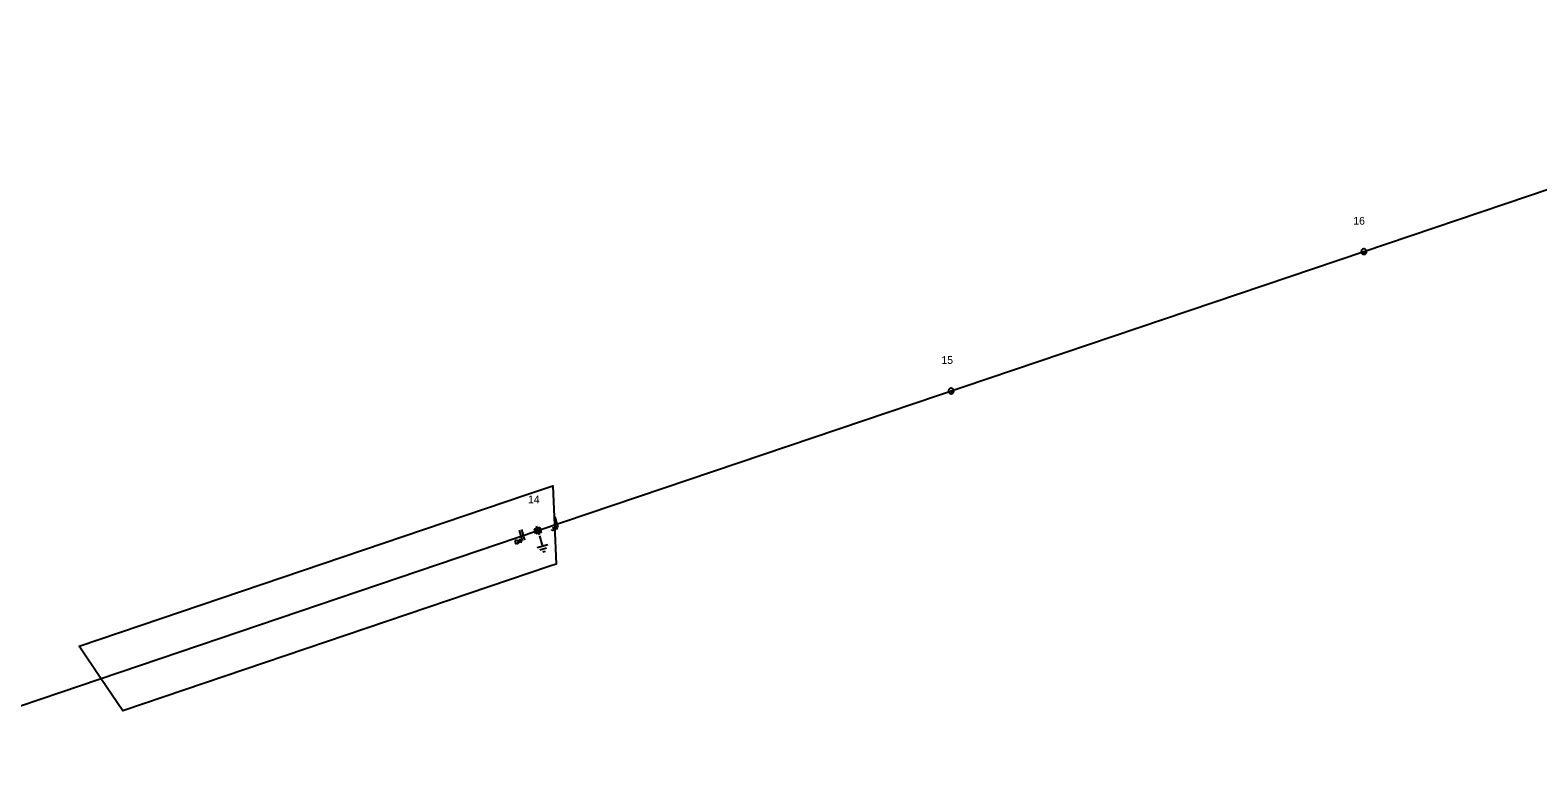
# Model space of a CAD drawing. Extents: x -788491 to -785797, y -1154753 to -1152002.
# Drawn here: x -786477.8 to -786137.2, y -1153308.2 to -1153143.3 of the extents above; entities that cross this region are included whole.
import ezdxf

# ---------------------------------------------------------------- set-up
doc = ezdxf.new("R2010")
doc.units = 0
for name, color, linetype in [('Vrstva 1', 7, 'Continuous'), ('Vrstva 13', 7, 'Continuous'), ('Vrstva 14', 7, 'Continuous'), ('Vrstva 15', 7, 'Continuous'), ('Vrstva 18', 7, 'Continuous'), ('Vrstva 2', 7, 'Continuous'), ('Vrstva 35', 7, 'Continuous')]:
    doc.layers.add(name, color=color, linetype=linetype)

# ---------------------------------------------------------------- blocks, each defined once
blk = doc.blocks.new('VN850')
at = {"layer": 'Vrstva 15'}
for points in [[(-0.56, 1.43), (-0.56, -1.07)], [(-0.01, 1.43), (-0.01, -1.07)], [(-2.09, -0.54), (-1.78, -0.54)], [(-2.09, -1.41), (-2.09, -0.54)], [(-1.78, -1.41), (-2.09, -1.41)], [(-1.78, -0.54), (-1.66, -0.6)], [(-1.67, -1.35), (-1.78, -1.41)], [(-1.59, -1.2), (-1.67, -1.35)], [(-1.66, -0.6), (-1.59, -0.75)], [(-1.59, -0.75), (-1.55, -0.96)], [(-1.55, -0.96), (-1.59, -1.2)], [(-1.26, -0.54), (-1.26, -1.41)], [(-0.85, -0.54), (-1.26, -1.09)], [(-1.13, -0.92), (-0.77, -1.41)]]:
    blk.add_lwpolyline(points, dxfattribs=at)
blk = doc.blocks.new('VN840')
at = {"layer": 'Vrstva 15'}
for points in [[(-0.01, 1.41), (-0.01, -1.09)], [(-1.51, -1.24), (-1.51, -1.15)], [(-1.48, -1.35), (-1.51, -1.24)], [(-1.33, -1.42), (-1.48, -1.35)], [(-1.27, -1.42), (-1.33, -1.42)], [(-1.13, -1.35), (-1.27, -1.42)], [(-1.09, -1.24), (-1.13, -1.35)], [(-1.09, -0.59), (-1.09, -1.24)], [(-0.68, -0.59), (-0.68, -1.42)], [(-0.68, -1.11), (-0.27, -0.59)], [(-0.54, -0.94), (-0.2, -1.42)]]:
    blk.add_lwpolyline(points, dxfattribs=at)
blk = doc.blocks.new('VN440')
at = {"layer": 'Vrstva 2'}
for points in [[(1.22, 0), (1.21, 0.13), (1.19, 0.25), (1.16, 0.38), (1.11, 0.5), (1.05, 0.61), (0.98, 0.72), (0.9, 0.82), (0.81, 0.91), (0.71, 0.99), (0.6, 1.06), (0.49, 1.12), (0.37, 1.16), (0.25, 1.2), (0.12, 1.22), (-0.01, 1.22), (-0.14, 1.22), (-0.26, 1.2), (-0.39, 1.16), (-0.51, 1.12), (-0.62, 1.06), (-0.73, 0.99), (-0.83, 0.91), (-0.92, 0.82), (-1, 0.72), (-1.07, 0.61), (-1.13, 0.5), (-1.18, 0.38), (-1.21, 0.25), (-1.23, 0.13), (-1.24, 0), (-1.23, -0.13), (-1.21, -0.26), (-1.18, -0.38), (-1.13, -0.5), (-1.07, -0.62), (-1, -0.73), (-0.92, -0.83), (-0.83, -0.92), (-0.73, -1), (-0.62, -1.07), (-0.51, -1.13), (-0.39, -1.17), (-0.26, -1.2), (-0.14, -1.23), (-0.01, -1.23), (0.12, -1.23), (0.25, -1.2), (0.37, -1.17), (0.49, -1.13), (0.6, -1.07), (0.71, -1), (0.81, -0.92), (0.9, -0.83), (0.98, -0.73), (1.05, -0.62), (1.11, -0.5), (1.16, -0.38), (1.19, -0.26), (1.21, -0.13), (1.22, 0)], [(-1.24, 0), (1.22, 0)], [(-1.18, -0.34), (1.1, -0.34)], [(-1.01, -0.63), (0.97, -0.63)], [(-0.74, -0.92), (0.68, -0.92)]]:
    blk.add_lwpolyline(points, dxfattribs=at)
blk = doc.blocks.new('VN810')
at = {"layer": 'Vrstva 14'}
for points in [[(0, -1.25), (0, -3.75)], [(1.25, -3.75), (-1.25, -3.75)], [(0.77, -4.37), (-0.8, -4.37)], [(0, -5), (-0.25, -5)], [(0.27, -5), (0, -5)]]:
    blk.add_lwpolyline(points, dxfattribs=at)
blk = doc.blocks.new('VN470')
at = {"layer": 'Vrstva 2'}
for points in [[(-1.23, 1.22), (1.23, 1.22)], [(-1.23, -1.23), (-1.23, 1.22)], [(-0.92, 0.9), (0.92, 0.9)], [(-0.92, -0.95), (-0.92, 0.9)], [(-0.61, 0.61), (0.61, 0.61)], [(-0.61, -0.62), (-0.61, 0.61)], [(-0.31, -0.27), (-0.31, 0.34)], [(-0.31, 0.34), (0.31, 0.34)], [(0, 1.22), (0, 1.97)], [(0.31, 0.34), (0.31, -0.27)], [(0.61, 0.61), (0.61, -0.62)], [(0.92, 0.9), (0.92, -0.95)], [(1.23, 1.22), (1.23, -1.23)], [(1.23, -1.23), (-1.23, -1.23)], [(0.92, -0.95), (-0.92, -0.95)], [(0.61, -0.62), (-0.61, -0.62)], [(0.31, -0.27), (-0.31, -0.27)], [(0, -1.23), (0, -1.98)]]:
    blk.add_lwpolyline(points, dxfattribs=at)

msp = doc.modelspace()

# ---------------------------------------------------------------- linework, layer by layer
at = {"layer": 'Vrstva 1'}
msp.add_lwpolyline([(-786516.04, -1153308.16), (-786363.07, -1153256.35), (-786176.45, -1153193.34), (-786028.55, -1153143.31)], dxfattribs=at)
at = {"layer": 'Vrstva 35'}
msp.add_lwpolyline([(-786359.32, -1153255.09), (-786358.94, -1153263.93), (-786360.34, -1153264.4), (-786456.85, -1153297.09), (-786461.79, -1153289.79), (-786466.71, -1153282.5), (-786365.79, -1153248.3), (-786359.7, -1153246.24)], close=True, dxfattribs=at)

# ---------------------------------------------------------------- block references
at = {"layer": 'Vrstva 13', "xscale": 0.5, "yscale": 0.5, "rotation": 16.067366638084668}
for name, p in [('VN440', (-786176.45, -1153193.34)), ('VN440', (-786269.7, -1153224.83)), ('VN470', (-786363.07, -1153256.35))]:
    msp.add_blockref(name, p, dxfattribs=at)
at = {"layer": 'Vrstva 15', "rotation": 16.067366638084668}
msp.add_blockref('VN810', (-786363.07, -1153256.35), dxfattribs=at)
at = {"layer": 'Vrstva 18', "rotation": 16.067366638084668}
for name, p in [('VN840', (-786358.81, -1153254.63)), ('VN850', (-786366.36, -1153257.48))]:
    msp.add_blockref(name, p, dxfattribs=at)

# ---------------------------------------------------------------- texts
at = {"layer": 'Vrstva 14'}
for s, p in [('16', (-786178.83, -1153187.25)), ('15', (-786271.88, -1153218.71)), ('14', (-786365.29, -1153250.21))]:
    msp.add_text(s, height=1.75, dxfattribs=at).set_placement(p)

doc.saveas('drawing.dxf')
